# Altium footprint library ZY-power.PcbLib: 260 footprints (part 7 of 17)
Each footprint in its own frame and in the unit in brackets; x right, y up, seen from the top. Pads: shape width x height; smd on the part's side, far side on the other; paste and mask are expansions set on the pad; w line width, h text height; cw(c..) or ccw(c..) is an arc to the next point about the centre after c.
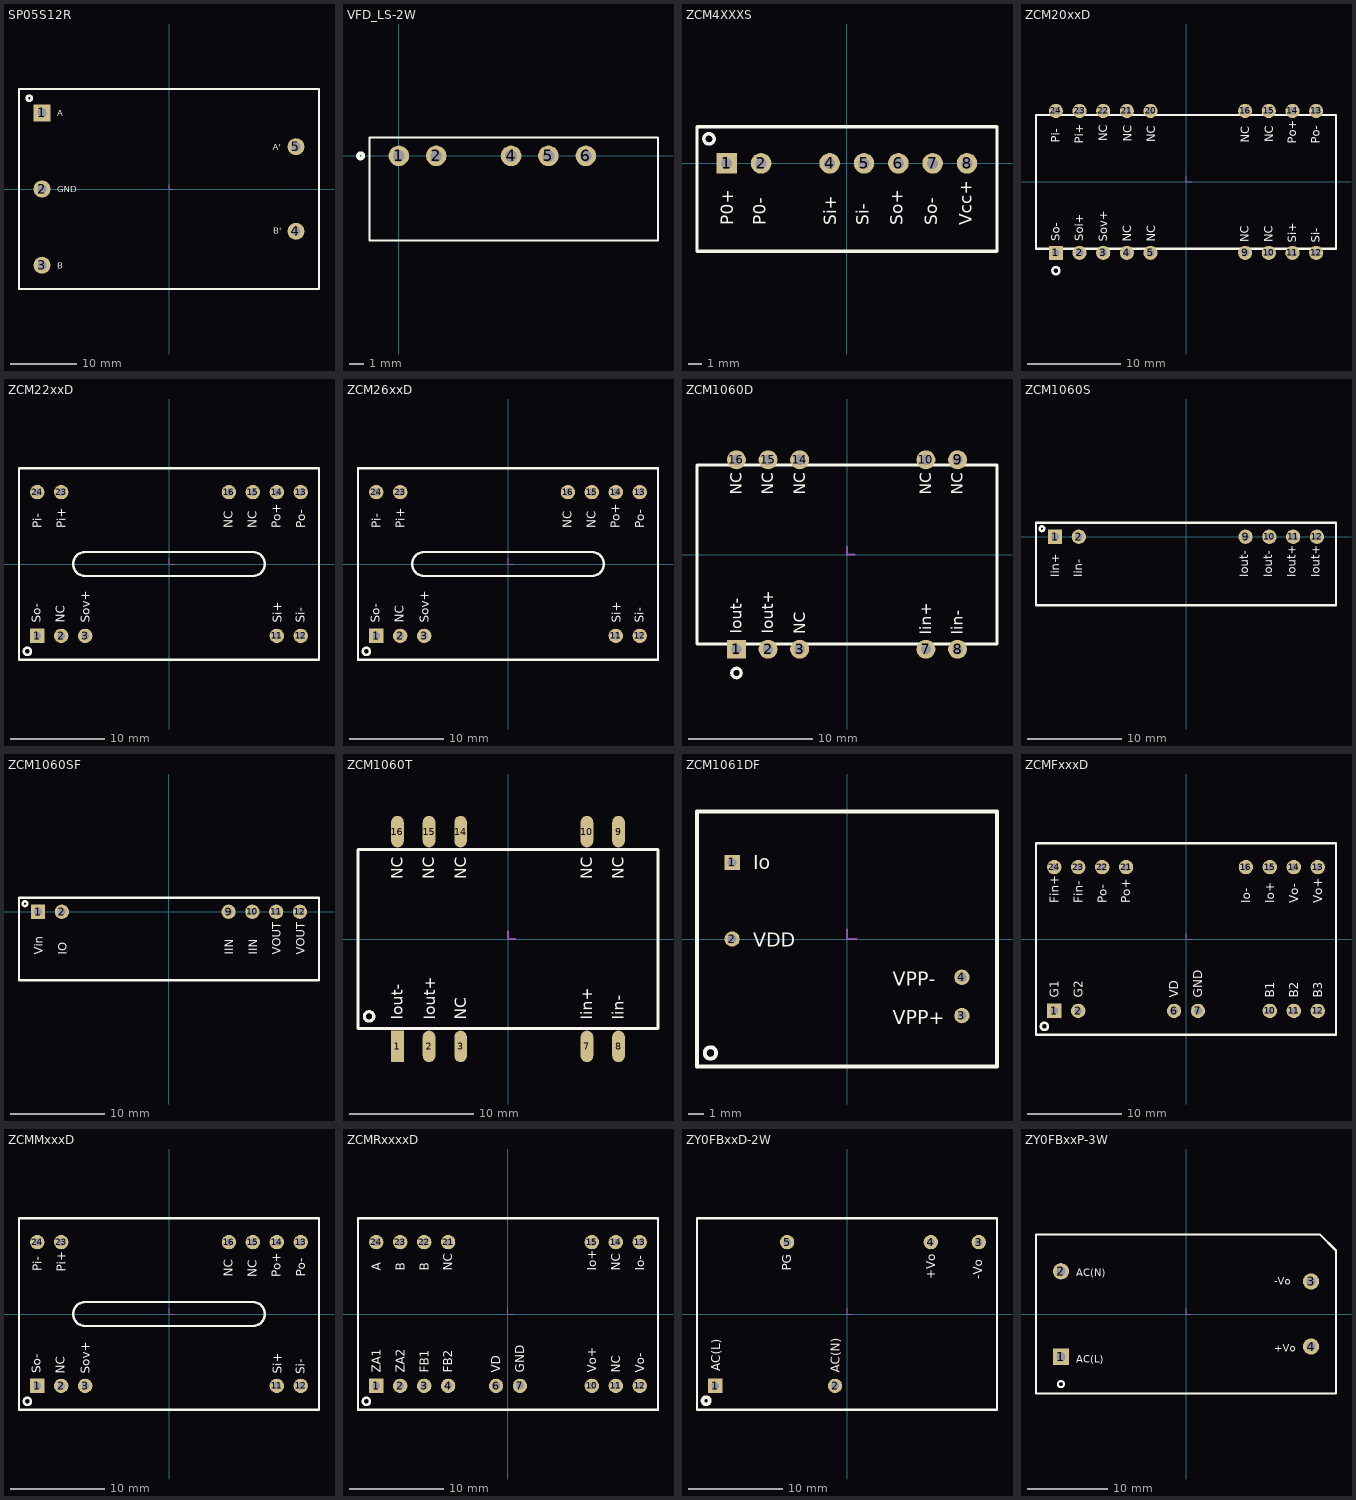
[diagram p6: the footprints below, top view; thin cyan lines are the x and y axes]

## SP05S12R [mil]
height 834.65
pads (5):
  rect 100x100 hole 55: 1(-750,450)
  round 100 hole 55: 2(-750,0) 3(-750,-450) 4(750,-250) 5(750,250)
Top Overlay:
  circle w15: c-825,536 r15
  lines w10: -885.83,-590.55 -885.83,590.55 885.83,590.55 885.83,-590.55 -885.83,-590.55
  text "B" at -660,-470 h36
  text "A" at -660,431 h36
  text "GND" at -660,-19.5 h36
  text "A'" at 612.23,230 h36
  text "B'" at 616,-265 h36
Mechanical 15:
  lines w5: 0,25 0,0 25,0

## VFD_LS-2W [mm]
pads (5):
  round 1.4 hole 0.8: 1(0,0) 2(2.54,0) 4(7.62,0) 5(10.16,0) 6(12.7,0)
Top Overlay:
  circle w0.254: c-2.593,0 r0.18
  lines w0.127: -2,-5.75 17.6,-5.75 17.6,1.25 -2,1.25 -2,-5.75

## ZCM4XXXS [mil]
pads (7):
  rect 60x60 hole 32: 1(-350,0)
  round 60 hole 32: 2(-250,0) 4(-50,0) 5(50,0) 6(150,0) 7(250,0) 8(350,0)
Top Overlay:
  circle w10: c-401.61,71.3 r15
  lines w10: -436.61,-255.91 -436.61,106.3 437.4,106.3 437.4,-255.91 -436.61,-255.91
  text "P0+" at -331.61,-180 h36
  text "P0-" at -236.61,-180 h36
  text "Si+" at -31.61,-180 h36
  text "Si-" at 63.39,-180 h36
  text "So+" at 163.39,-180 h36
  text "So-" at 263.39,-180 h36
  text "Vcc+" at 363.39,-180 h36

## ZCM20xxD [mil]
height 689
pads (18):
  rect 60x60 hole 32: 1(-550,-300)
  round 60 hole 32: 2(-450,-300) 3(-350,-300) 4(-250,-300) 5(-150,-300) 9(250,-300) 10(350,-300) 11(450,-300) 12(550,-300) 13(550,300) 14(450,300) 15(350,300) 16(250,300) 20(-150,300) 21(-250,300) 22(-350,300) 23(-450,300) 24(-550,300)
Top Overlay:
  circle w10: c-550,-375 r15
  lines w10: -634,-283 634,-283 634,283 -634,283 -634,-283
  text "Si+" at 466,-257 h36
  text "Soi+" at -434,-251 h36
  text "NC" at -230,170 h36
  text "So-" at -534,-251 h36
  text "NC" at -129,167 h36
  text "NC" at -332,171 h36
  text "NC" at 268,165 h36
  text "NC" at 368,167 h36
  text "Sov+" at -332,-252 h36
  text "NC" at -131,-253 h36
  text "NC" at -231,-253 h36
  text "NC" at 366,-256 h36
  text "NC" at 266,-256 h36
  text "Si-" at 566,-257 h36
  text "Po-" at 566,161 h36
  text "Po+" at 466,161 h36
  text "Pi+" at -434,162 h36
  text "Pi-" at -534,166 h36
Mechanical 15:
  lines w5: 0,25 0,0 25,0

## ZCM22xxD [mil]
height 374.02
pads (11):
  rect 60x60 hole 32: 1(-550,-300)
  round 60 hole 32: 2(-450,-300) 3(-350,-300) 11(450,-300) 12(550,-300) 13(550,300) 14(450,300) 15(350,300) 16(250,300) 23(-450,300) 24(-550,300)
Top Overlay:
  circle w10: c-590.98,-364.61 r15
  lines w10: -550,-399.61 -551.38,-399.61 ; -551.38,-399.61 -625.98,-399.61 -625.98,399.61 625.98,399.61 625.98,-399.61 -551.38,-399.61 ; -400,0 cw(c-350,0) -350,50 350,50 cw(c350,0) 400,0 cw(c350,0) 350,-50 -350,-50 cw(c-350,0) -400,0
  text "NC" at 267,150 h36
  text "NC" at 367,150 h36
  text "Po-" at 568,150 h36
  text "Si-" at 567,-245 h36
  text "So-" at -535,-245 h36
  text "Si+" at 470,-245 h36
  text "NC" at -435,-245 h36
  text "Sov+" at -330,-245 h36
  text "Pi-" at -532,150 h36
  text "Pi+" at -430,150 h36
  text "Po+" at 466,150 h36
Mechanical 15:
  lines w5: 0,25 0,0 25,0

## ZCM26xxD [mil]
height 374.02
pads (11):
  rect 60x60 hole 32: 1(-550,-300)
  round 60 hole 32: 2(-450,-300) 3(-350,-300) 11(450,-300) 12(550,-300) 13(550,300) 14(450,300) 15(350,300) 16(250,300) 23(-450,300) 24(-550,300)
Top Overlay:
  circle w10: c-590.98,-364.61 r15
  lines w10: -550,-399.61 -551.38,-399.61 ; -551.38,-399.61 625.98,-399.61 625.98,399.61 -625.98,399.61 -625.98,-399.61 -551.38,-399.61 ; -400,0 ccw(c-350,0) -350,-50 350,-50 ccw(c350,0) 400,0 ccw(c350,0) 350,50 -350,50 ccw(c-350,0) -400,0
  text "Po+" at 466,150 h36
  text "Pi+" at -430,150 h36
  text "Pi-" at -532,150 h36
  text "Sov+" at -330,-245 h36
  text "NC" at -435,-245 h36
  text "Si+" at 470,-245 h36
  text "So-" at -535,-245 h36
  text "Si-" at 567,-245 h36
  text "Po-" at 568,150 h36
  text "NC" at 367,150 h36
  text "NC" at 267,150 h36
Mechanical 15:
  lines w5: 0,25 0,0 25,0

## ZCM1060D [mil]
height 393.7
pads (10):
  rect 60x60 hole 32: 1(-350,-300)
  round 60 hole 32: 2(-250,-300) 3(-150,-300) 7(250,-300) 8(350,-300) 9(350,300) 10(250,300) 14(-150,300) 15(-250,300) 16(-350,300)
Top Overlay:
  circle w10: c-350,-375 r15
  lines w10: -475,-283 -475,283 475,283 475,-283 -475,-283
  text "NC" at -132,-252 h36
  text "NC" at 367,190 h36
  text "NC" at 267,190 h36
  text "NC" at -133,190 h36
  text "NC" at -333,190 h36
  text "Iout-" at -334,-251 h36
  text "NC" at -233,190 h36
  text "Iout+" at -234,-251 h36
  text "Iin-" at 367,-254 h36
  text "Iin+" at 267,-254 h36
Mechanical 15:
  lines w5: 0,25 0,0 25,0

## ZCM1060S [mil]
height 582.68
pads (6):
  rect 60x60 hole 32: 1(-550,0)
  round 60 hole 32: 2(-450,0) 9(250,0) 10(350,0) 11(450,0) 12(550,0)
Top Overlay:
  circle w10: c-604.92,34.06 r10
  lines w10: -629.92,-287.4 629.92,-287.4 629.92,59.06 -629.92,59.06 -629.92,-287.4
  text "Iout+" at 562,-170 h36
  text "Iout+" at 461.39,-170 h36
  text "Iout-" at 361.39,-170 h36
  text "Iout-" at 261.39,-170 h36
  text "Iin-" at -436.61,-170 h36
  text "Iin+" at -531.61,-170 h36

## ZCM1060SF [mil]
height 582.68
pads (6):
  rect 60x60 hole 32: 1(-550,0)
  round 60 hole 32: 2(-450,0) 9(250,0) 10(350,0) 11(450,0) 12(550,0)
Top Overlay:
  circle w10: c-604.92,34.06 r10
  lines w10: -629.92,-287.4 629.92,-287.4 629.92,59.06 -629.92,59.06 -629.92,-287.4
  text "VOUT" at 570.08,-180 h36
  text "VOUT" at 470.08,-180 h36
  text "IIN" at 370.08,-180 h36
  text "IIN" at 270.08,-180 h36
  text "IO" at -429.92,-180 h36
  text "Vin" at -529.92,-180 h36

## ZCM1060T [mil]
height 393.7
pads (10):
  rect 40x100 smd: 1(-350,-340)
  oval 40x100 smd: 2(-250,-340) 3(-150,-340) 7(250,-340) 8(350,-340) 9(350,340) 10(250,340) 14(-150,340) 15(-250,340) 16(-350,340)
Top Overlay:
  circle w10: c-440,-245 r15
  lines w10: -475,-283 475,-283 475,283 -475,283 -475,-283
  text "Iin+" at 267,-255 h36
  text "Iin-" at 367,-255 h36
  text "Iout+" at -230,-255 h36
  text "NC" at -233,190 h36
  text "Iout-" at -334,-255 h36
  text "NC" at -333,190 h36
  text "NC" at -133,190 h36
  text "NC" at 267,190 h36
  text "NC" at 367,190 h36
  text "NC" at -132,-255 h36
Mechanical 15:
  lines w5: 0,25 0,0 25,0

## ZCM1061DF [mil]
height 277.56
pads (4):
  rect 40x40 hole 24: 1(-300,200)
  round 40 hole 24: 2(-300,0) 3(300,-200) 4(300,-100)
Top Overlay:
  circle w10: c-356.73,-297.58 r15
  lines w10: -391.73,-332.58 -391.73,332.78 391.73,332.78 391.73,-332.58 -391.73,-332.58
  text "VPP+" at 120,-222.78 h36
  text "VPP-" at 120,-121.78 h36
  text "Io" at -245,182.78 h36
  text "VDD" at -245,-20 h36
Mechanical 15:
  lines w5: 0,25 0,0 25,0

## ZCMFxxxD [mil]
pads (15):
  rect 60x60 hole 32: 1(-550,-300)
  round 60 hole 32: 2(-450,-300) 6(-50,-300) 7(50,-300) 10(350,-300) 11(450,-300) 12(550,-300) 13(550,300) 14(450,300) 15(350,300) 16(250,300) 21(-250,300) 22(-350,300) 23(-450,300) 24(-550,300)
Top Overlay:
  circle w10: c-590.98,-364.61 r15
  lines w10: -625.98,-399.61 625.98,-399.61 625.98,399.61 -625.98,399.61 -625.98,-399.61
  text "Fin+" at -531.61,150 h36
  text "Fin-" at -431.61,150 h36
  text "Po-" at -331.61,150 h36
  text "Po+" at -231.61,150 h36
  text "Io-" at 268.39,150 h36
  text "Io+" at 368.39,150 h36
  text "Vo-" at 468.39,150 h36
  text "Vo+" at 568.39,150 h36
  text "G1" at -531.61,-245 h36
  text "G2" at -431.61,-245 h36
  text "VD" at -31.61,-245 h36
  text "GND" at 68.39,-245 h36
  text "B1" at 368.39,-245 h36
  text "B2" at 468.39,-245 h36
  text "B3" at 568.39,-245 h36
Mechanical 15:
  lines w5: 0,25 0,0 25,0

## ZCMMxxxD [mil]
height 374.02
pads (11):
  rect 60x60 hole 32: 1(-550,-300)
  round 60 hole 32: 2(-450,-300) 3(-350,-300) 11(450,-300) 12(550,-300) 13(550,300) 14(450,300) 15(350,300) 16(250,300) 23(-450,300) 24(-550,300)
Top Overlay:
  circle w10: c-590.98,-364.61 r15
  lines w10: -550,-399.61 -551.38,-399.61 ; -551.38,-399.61 625.98,-399.61 625.98,399.61 -625.98,399.61 -625.98,-399.61 -551.38,-399.61 ; -400,0 ccw(c-350,0) -350,-50 350,-50 ccw(c350,0) 400,0 ccw(c350,0) 350,50 -350,50 ccw(c-350,0) -400,0
  text "Po+" at 466,154 h36
  text "Pi+" at -430,177 h36
  text "Pi-" at -532,178 h36
  text "Sov+" at -330,-250 h36
  text "NC" at -435,-250 h36
  text "Si+" at 470,-250 h36
  text "So-" at -535,-247 h36
  text "Si-" at 567,-251 h36
  text "Po-" at 568,155 h36
  text "NC" at 367,153 h36
  text "NC" at 267,155 h36
Mechanical 15:
  lines w5: 0,25 0,0 25,0

## ZCMRxxxxD [mil]
pads (16):
  rect 60x60 hole 32: 1(-550,-300)
  round 60 hole 32: 2(-450,-300) 3(-350,-300) 4(-250,-300) 6(-50,-300) 7(50,-300) 10(350,-300) 11(450,-300) 12(550,-300) 13(550,300) 14(450,300) 15(350,300) 21(-250,300) 22(-350,300) 23(-450,300) 24(-550,300)
Top Overlay:
  circle w10: c-590.98,-364.61 r15
  lines w10: -625.98,-399.61 -625.98,399.61 625.98,399.61 625.98,-399.61 -625.98,-399.61
  text "A" at -531.61,180 h36
  text "B" at -431.61,180 h36
  text "B" at -331.61,180 h36
  text "NC" at -231.61,180 h36
  text "Io+" at 368.39,180 h36
  text "NC" at 468.39,180 h36
  text "Io-" at 568.39,180 h36
  text "ZA1" at -531.61,-245 h36
  text "ZA2" at -431.61,-245 h36
  text "VD" at -31.61,-245 h36
  text "GND" at 68.39,-245 h36
  text "Vo+" at 368.39,-245 h36
  text "NC" at 468.39,-245 h36
  text "Vo-" at 568.39,-245 h36
  text "FB2" at -231.61,-245 h36
  text "FB1" at -331.61,-245 h36
Mechanical 15:
  lines w5: 0,25 0,0 25,0

## ZY0FBxxD-2W [mil]
height 413.39
pads (5):
  rect 60x60 hole 32: 1(-550,-300)
  round 60 hole 32: 2(-50,-300) 3(550,300) 4(350,300) 5(-250,300)
Top Overlay:
  circle w15: c-587.98,-362 r15
  lines w10: -625.98,-399.61 -625.98,399.61 625.98,399.61 625.98,-399.61 -625.98,-399.61
  text "PG" at -232,181 h36
  text "AC(N)" at -31,-245 h36
  text "-Vo" at 565,145 h36
  text "+Vo" at 369,146 h36
  text "AC(L)" at -530,-239 h36
Mechanical 15:
  lines w5: 0,25 0,0 25,0

## ZY0FBxxP-3W [mil]
pads (4):
  rect 80x80 hole 45: 1(-615,-210)
  round 80 hole 45: 2(-615,210) 3(615,160) 4(615,-160)
Top Overlay:
  circle w10: c-615,-345 r15
  lines w10: -737.68,-391.69 737.68,-391.69 737.68,312.31 658.32,391.69 -737.68,391.69 -737.68,-391.69
  text "AC(L)" at -540,-240 h36
  text "AC(N)" at -540,185 h36
  text "-Vo" at 435,145 h36
  text "+Vo" at 435,-185 h36
Mechanical 15:
  lines w5: 0,25 0,0 25,0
